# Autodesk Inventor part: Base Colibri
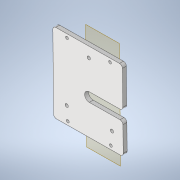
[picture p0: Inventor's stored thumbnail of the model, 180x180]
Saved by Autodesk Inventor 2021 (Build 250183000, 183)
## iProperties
Created: 2021-03
Part Number: Base Colibri
Material: Genérico
Document SubType Name: Modeling
Designer: ATOUZA
Density: 1 g/cm^3
Appearance: Valor por defecto
Author: ATOUZA
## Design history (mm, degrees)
node "Plano de trabajo1"
sketch "Boceto1"
  geometry: L1 (33.008, 55.056)-(-63.941, 54.94); L2 (22.995, -1.756)-(23.038, -37.956) reference; L3 (26.995, -1.751)-(22.995, -1.756) reference; L4 (26.989, 3.049)-(26.995, -1.751) reference; L5 (53.989, 3.082)-(26.989, 3.049) reference; L6 (53.938, 45.082)-(53.989, 3.082) reference; L7 (-47.062, 44.96)-(53.938, 45.082) reference; L8 (-53.962, -38.048)-(-54.053, 37.952) reference; L9 (16.047, -44.964)-(-46.953, -45.04) reference; L10 (-44.333, 132.372)-(-43.877, -247.628); L11 (28.95, -246.94)-(11.45, -246.961) reference; L12 (15.667, 132.444)-(16.123, -247.556); L13 (-13.941, -12.628)-(33.023, -12.571); L14 (33.023, -12.571)-(33.125, -54.972); L15 (33.125, -54.972)-(-63.941, -54.972); L16 (-63.941, -54.972)-(-63.941, 54.94); L17 (33.008, 0.228)-(33.008, 55.056); L18 (-13.9, 0.172)-(33.008, 0.228); C1 r 2.25 at (-45.419, -31.764) reference; C2 r 2.25 at (-13.956, 40.7) reference; C3 r 2.25 at (17.681, -31.689) reference; C4 r 2.25 at (-13.956, 40.7); C5 r 2.25 at (17.681, -31.689); C6 r 2.25 at (-45.419, -31.764); C7 r 2 at (-44.114, -50.036); C8 r 2 at (15.766, 50.036); C9 r 2 at (-44.234, 49.964); C10 r 2 at (15.886, -49.964); A1 r 6.4 centre (-13.892, -6.228) between (-13.84, 0.171) and (-13.828, -12.628); A2 r 6.4 centre (-13.892, -6.228) between (-13.84, 0.171) and (-13.828, -12.628); A3 r 7 centre (16.038, -37.964) between (16.047, -44.964) and (23.038, -37.956) reference; A4 r 7 centre (-47.053, 37.96) between (-47.062, 44.96) and (-54.053, 37.952) reference; A5 r 7 centre (-46.962, -38.04) between (-53.962, -38.048) and (-46.953, -45.04) reference; A6 r 6.4 centre (-13.892, -6.228) between (-13.84, 0.171) and (-13.828, -12.628); A7 r 2 centre (55.667, 132.492) between (56.622, 130.735) and (56.618, 134.251) reference; A8 r 2 centre (35.667, 132.468) between (36.622, 130.711) and (36.618, 134.227) reference; A9 r 2 centre (15.667, 132.444) between (16.622, 130.687) and (16.618, 134.203) reference; A10 r 2 centre (-4.333, 132.42) between (-3.378, 130.663) and (-3.382, 134.179) reference; A11 r 2 centre (-24.333, 132.396) between (-23.378, 130.639) and (-23.382, 134.155) reference; A12 r 2 centre (-44.333, 132.372) between (-43.378, 130.615) and (-43.382, 134.131) reference; A13 r 2 centre (-64.333, 132.348) between (-63.378, 130.591) and (-63.382, 134.107) reference; A14 r 2 centre (-84.333, 132.324) between (-83.378, 130.567) and (-83.382, 134.083) reference; A15 r 2 centre (-43.877, -247.628) between (-42.921, -249.385) and (-42.925, -245.868) reference; A16 r 2 centre (-63.877, -247.652) between (-62.921, -249.409) and (-62.925, -245.892) reference; A17 r 2 centre (-83.877, -247.676) between (-82.921, -249.433) and (-82.925, -245.917) reference; A18 r 2 centre (16.123, -247.556) between (17.079, -249.312) and (17.075, -245.796) reference; A19 r 6.4 centre (-13.892, -6.228) between (-13.84, 0.171) and (-13.828, -12.628); 3 further points
  constraints: 18 end point, 11 centre point, 10 point on circle, 5 coincident, 5 point on line, 4 concentric, 4 tangent, 2 parallel, 1 horizontal, 1 vertical
  dimensions: "d1" = 10 distance between parallel lines of L1 L7; "d7" = 4 diameter of C7; "d9" = 4 diameter of C8; "d10" = 4 diameter of C9; "d11" = 4 diameter of C10; "d12" = 5 distance from line of L9 C7.centre; "d13" = 5 distance from line of L9 C10.centre; "d14" = 5 distance from line of L7 C9.centre; "d15" = 5 distance from line of L7 C8.centre
extrude "Extrusión1" new body sketch "Boceto1" distance "d5" = 5.5; taper "d6" = 0 deg
fillet "Empalme1" dims "d16" = 4
node "Sólido1"
node "Referencia3"
node "Referencia4"
node "Referencia5"
node "Referencia6"
node "Referencia7"
node "Referencia8"
node "Referencia9"
node "Referencia10"
node "Referencia11"
node "Referencia12"
node "Referencia13"
node "Referencia15"
node "Referencia16"
